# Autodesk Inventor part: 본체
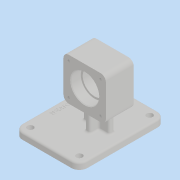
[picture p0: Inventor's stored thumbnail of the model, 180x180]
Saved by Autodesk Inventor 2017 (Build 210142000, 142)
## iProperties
Part Number: 본체
Material: 일반
Document SubType Name: Modeling
Designer: mrc
Density: 1 g/cm^3
Appearance: 기본값
Mass: 253.042 g
Surface Area: 542.794 cm^2
Volume: 253.042 cm^3
Author: mrc
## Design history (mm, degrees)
sketch "스케치1"
  geometry: L1 (65, 49)-(-65, 49); L2 (-65, 49)-(-65, -49); L3 (-65, -49)-(65, -49); L4 (65, -49)-(65, 49); L5 (65, 49)-(-65, -49); L6 (-65, 49)-(65, -49); 1 further point
  constraints: 12 end point, 2 midpoint, 2 parallel, 1 horizontal, 1 perpendicular
  dimensions: "d0" = 130 distance of L2.end L3.end; "d1" = 98 distance of L1.end L2.end
extrude "돌출1" new body sketch "스케치1" distance "d2" = 10; taper "d3" = 0 deg
sketch "스케치3"
  geometry: L1 (-4, 7)-(4, 7); L2 (4, 7)-(4, -33); L3 (4, -33)-(-4, -33); L4 (-4, -33)-(-4, 7); L5 (-4, 7)-(4, -33); L6 (4, 7)-(-4, -33); L7 (-17, -17)-(17, -17); L8 (17, -17)-(17, -9); L9 (17, -9)-(-17, -9); L10 (-17, -9)-(-17, -17); L11 (-17, -17)-(17, -9); L12 (17, -17)-(-17, -9); L13 (65, -49)-(65, 49) reference; L14 (65, 49)-(-65, 49) reference; 2 further points
  constraints: 24 end point, 5 midpoint, 4 parallel, 2 horizontal, 2 perpendicular
  dimensions: "d9" = 65 distance from line of L13 point (0, -13); "d10" = 62 distance from line of L14 point (0, -13); "d11" = 8 distance between parallel lines of L2 L4; "d12" = 8 distance between parallel lines of L7 L9; "d13" = 34 distance between parallel lines of L8 L10; "d14" = 40 distance between parallel lines of L1 L3
sketch "스케치8"
  geometry: L1 (38, -19)-(102, -19); L2 (102, -19)-(102, 45); L3 (102, 45)-(38, 45); L4 (38, 45)-(38, -19); L5 (38, -19)-(102, 45); L6 (102, -19)-(38, 45); L7 (0, -49)-(10, -49) reference; L8 (0, -49)-(0, 49) reference; 2 further points
  constraints: 12 end point, 2 midpoint, 2 parallel, 1 horizontal, 1 perpendicular
  dimensions: "d33" = 62 distance from line of L7 point (70, 13); "d34" = 70 distance from line of L8 point (70, 13); "d35" = 64 distance of L1.end L2.end; "d36" = 64 distance of L2.end L3.end
extrude "돌출7" join sketch "스케치8" stored distance "d37" = 42; taper "d38" = 0 deg
extrude "돌출8" join sketch "스케치3" stored distance "d39" = 42; taper "d40" = 0 deg
sketch "스케치9"
  geometry: L1 (45, 102)-(-19, 102) reference; L2 (-19, 102)-(-19, 38) reference; C1 r 21 at (13, 70); 3 further points
  constraints: 2 midpoint, 1 centre point, 1 horizontal alignment, 1 vertical alignment
  dimensions: "d41" = 42 diameter of C1
extrude "돌출9" cut sketch "스케치9" distance "d42" = 15; taper "d43" = 0 deg
sketch "스케치10"
  geometry: C1 r 18 at (0, 0); C2 r 21 at (0, 0) reference; 1 further point
  constraints: 1 centre point, 1 concentric
  dimensions: "d44" = 36 diameter of C1
extrude "돌출10" cut sketch "스케치10" distance "d45" = 40.5; taper "d46" = 0 deg
fillet "모깎기1" dims "d47" = 12
fillet "모깎기2" dims "d48" = 8
sketch "스케치11"
  geometry: C1 r 18 at (13, 70) reference; 2 further points
  dimensions: "d49" = 24 horizontal distance of point (-11, 94) C1.centre; "d50" = 24 horizontal distance of C1.centre point (-11, 94)
hole "구멍1" sketch "스케치11" at (-11, 94) diameter "d51" = 3.242; stored, may be unused: countersink angle "d55" = 90 deg, drill point angle "d57" = 118 deg; dims "d52" = 8, "d53" = 4, "d54" = 2, "d56" = 10
fillet "모깎기3" dims "d64" = 3
fillet "모깎기4" dims "d65" = 3
fillet "모깎기5" dims "d66" = 0.3
chamfer "모따기1" distance "d67" = 1; stored, may be unused: second distance "d68" = 2, angle "d69" = 45 deg
sketch "스케치12"
  geometry: L1 (65, -37)-(65, 37) reference; L2 (53, 49)-(-53, 49) reference; 2 further points
  constraints: 1 other
  dimensions: "d70" = 65 distance from line of L1 point (0, 39); "d71" = 10 distance from line of L2 point (0, 39)
feature "엠보싱1" sketch "스케치12" dims "d0" = 130, "d1" = 98, "d9" = 65, "d10" = 62, "d11" = 8, "d12" = 8, "d13" = 34, "d14" = 40, "d72" = 0.5, "d73" = 0
sketch "스케치13"
  geometry: C1 r 4.5 at (-53, 37); C2 r 4.5 at (53, 37); C3 r 4.5 at (-53, -37); C4 r 4.5 at (53, -37); A1 r 12 centre (-53, 37) between (-53, 49) and (-65, 37) reference; A2 r 12 centre (53, 37) between (65, 37) and (53, 49) reference; A3 r 12 centre (53, -37) between (53, -49) and (65, -37) reference; A4 r 12 centre (-53, -37) between (-65, -37) and (-53, -49) reference; 1 further point
  constraints: 4 centre point, 2 coincident, 2 concentric
  dimensions: "d74" = 9 diameter of C1; "d75" = 9 diameter of C2; "d76" = 9 diameter of C3; "d77" = 9 diameter of C4
extrude "돌출11" cut sketch "스케치13" distance "d78" = 40.5; taper "d79" = 0 deg
node "솔리드1"
mirror "미러1"
pattern_linear "직사각형 패턴1" dims "d60" = 48, "d63" = 48
mirror "미러2"
